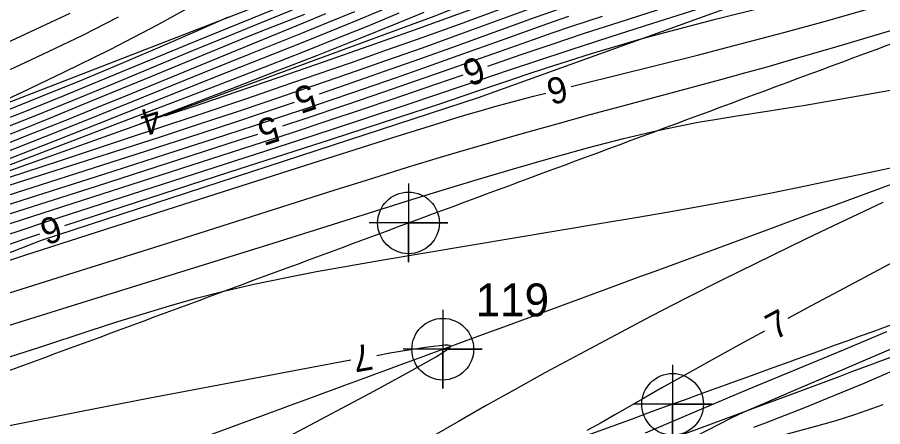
# Model space of a CAD drawing. Extents: x 2602990 to 2605851, y 618069 to 619180.
# Drawn here: x 2603621.3 to 2603687.1, y 618530.5 to 618561.6 of the extents above; entities that cross this region are included whole.
import ezdxf

# ---------------------------------------------------------------- set-up
doc = ezdxf.new("R2010")
doc.units = 0
for name, color, linetype in [('DTM Contours Major', 7, 'Continuous'), ('DTM Contours Major Text', 7, 'Continuous'), ('DTM Contours Minor', 7, 'Continuous'), ('DTM Contours Minor Text', 7, 'Continuous'), ('Exist DTM Breakline', 7, 'Continuous'), ('Exist DTM Crownline', 7, 'Continuous'), ('Exist DTM Crownline Cogo Number', 7, 'Continuous'), ('Exist DTM Crownline Cogo Point CELL', 7, 'Continuous'), ('Exist Roads EOP', 7, 'Continuous'), ('Exist Roads EOP Cogo Point CELL', 7, 'Continuous'), ('PH Exist DTM Breakline', 7, 'Continuous')]:
    doc.layers.add(name, color=color, linetype=linetype)

# ---------------------------------------------------------------- blocks, each defined once
blk = doc.blocks.new('EXIST DTM CROWNLINE COGO POINT')
at = {"layer": 'Exist DTM Crownline Cogo Point CELL'}
blk.add_lwpolyline([(0, 0.06), (0, -0.06), (0, 0), (0.06, 0), (-0.06, 0)], dxfattribs=at)
blk.add_circle((0, 0), 0.0469, dxfattribs=at)
blk = doc.blocks.new('EXIST ROADS EOP COGO POINT')
at = {"layer": 'Exist Roads EOP Cogo Point CELL'}
blk.add_lwpolyline([(0, 0.06), (0, -0.06), (0, 0), (0.06, 0), (-0.06, 0)], dxfattribs=at)
blk.add_circle((0, 0), 0.0469, dxfattribs=at)

msp = doc.modelspace()

# ---------------------------------------------------------------- linework, layer by layer
at = {"layer": 'DTM Contours Major'}
for points in [[(2603624.935, 618545.771), (2603626.021, 618546.13), (2603629.438, 618547.248), (2603637.398, 618549.827), (2603645.213, 618552.351), (2603650.317, 618554.009), (2603653.432, 618555.038), (2603656.165, 618555.96), (2603658.61, 618556.791), (2603660.004, 618557.259), (2603661.544, 618557.767), (2603663.202, 618558.301), (2603664.953, 618558.85), (2603666.771, 618559.399), (2603668.628, 618559.937), (2603670.546, 618560.465), (2603672.469, 618560.972), (2603674.386, 618561.462), (2603678.162, 618562.411)], [(2603637.358, 618561.62), (2603635.026, 618560.586), (2603632.324, 618559.413), (2603629.374, 618558.154), (2603626.3, 618556.865), (2603623.222, 618555.601), (2603620.265, 618554.416), (2603619.145, 618553.977), (2603618.05, 618553.555), (2603616.97, 618553.144), (2603615.891, 618552.742), (2603614.802, 618552.343), (2603613.691, 618551.942), (2603610.655, 618550.877), (2603607.494, 618549.799), (2603604.321, 618548.735), (2603598.384, 618546.757), (2603595.845, 618545.899), (2603594.187, 618545.324), (2603592.708, 618544.798), (2603590.596, 618544.03), (2603587.542, 618542.911), (2603586.705, 618542.609), (2603584.916, 618541.972)], [(2603583.669, 618530.573), (2603588.135, 618532.287), (2603590.546, 618533.197), (2603610.988, 618540.791), (2603616.719, 618542.909), (2603618.996, 618543.735), (2603620.082, 618544.121), (2603621.895, 618544.752), (2603623.038, 618545.137)], [(2603689.392, 618535.379), (2603685.655, 618533.76), (2603682.318, 618532.372), (2603681.15, 618531.909), (2603678.149, 618530.747), (2603677.269, 618530.396)]]:
    msp.add_lwpolyline(points, dxfattribs=at)
at = {"layer": 'DTM Contours Minor'}
for points in [[(2603581.739, 618530.696), (2603587.925, 618533.097), (2603589.528, 618533.709), (2603591.102, 618534.299), (2603598.1, 618536.876), (2603610.103, 618541.323), (2603613.987, 618542.753), (2603616.141, 618543.536), (2603618.127, 618544.242), (2603619.098, 618544.58), (2603620.189, 618544.952), (2603621.307, 618545.327), (2603623.708, 618546.117), (2603640.295, 618551.482), (2603643.652, 618552.574), (2603647.662, 618553.888), (2603651.114, 618555.038), (2603655.168, 618556.411), (2603658.818, 618557.651), (2603660.651, 618558.262), (2603663.331, 618559.139), (2603666.368, 618560.121), (2603669.621, 618561.164), (2603676.203, 618563.26)], [(2603635.401, 618562.914), (2603631.959, 618561.017), (2603628.344, 618559.146), (2603624.834, 618557.41), (2603621.71, 618555.918), (2603618.941, 618554.634), (2603617.838, 618554.139), (2603617.273, 618553.897), (2603616.758, 618553.691), (2603616.187, 618553.479), (2603615.47, 618553.226), (2603613.165, 618552.439), (2603610.041, 618551.39), (2603607.893, 618550.673)], [(2603659.771, 618562.855), (2603654.897, 618561.075), (2603651.719, 618559.932), (2603649.237, 618559.052), (2603646.686, 618558.157), (2603644.077, 618557.251), (2603641.422, 618556.338), (2603638.735, 618555.422), (2603634.816, 618554.1), (2603629.666, 618552.383), (2603624.505, 618550.677), (2603620.636, 618549.409), (2603618.129, 618548.599)], [(2603657.242, 618562.722), (2603653.242, 618561.274), (2603651.486, 618560.646), (2603648.038, 618559.425), (2603644.562, 618558.206), (2603641.196, 618557.038), (2603638.077, 618555.963), (2603635.342, 618555.03), (2603632.52, 618554.08)], [(2603640.896, 618562.233), (2603638.198, 618561.139), (2603635.096, 618559.864), (2603628.275, 618557.046), (2603624.851, 618555.641), (2603621.616, 618554.331), (2603620.027, 618553.699), (2603618.506, 618553.103), (2603617.028, 618552.534), (2603615.568, 618551.984), (2603614.101, 618551.444), (2603612.601, 618550.903), (2603609.985, 618549.986), (2603607.282, 618549.061), (2603599.402, 618546.404), (2603597.102, 618545.614), (2603596.063, 618545.249), (2603594.155, 618544.562), (2603592.403, 618543.915), (2603587.795, 618542.179), (2603585.767, 618541.429)], [(2603586.029, 618540.695), (2603588.38, 618541.586), (2603592.827, 618543.293), (2603594.926, 618544.083), (2603596.02, 618544.487), (2603597.158, 618544.9), (2603598.349, 618545.324), (2603600.382, 618546.032), (2603604.788, 618547.535), (2603607.085, 618548.317), (2603609.393, 618549.113), (2603611.674, 618549.916), (2603613.486, 618550.571), (2603615.277, 618551.234), (2603617.068, 618551.913), (2603618.879, 618552.615), (2603620.733, 618553.347), (2603622.649, 618554.116), (2603625.511, 618555.284), (2603628.473, 618556.507), (2603634.42, 618558.978), (2603637.262, 618560.155), (2603639.924, 618561.245), (2603643.363, 618562.631)], [(2603605.388, 618545.666), (2603607.602, 618546.474), (2603608.879, 618546.945), (2603611.531, 618547.937), (2603614.395, 618549.025), (2603617.386, 618550.176), (2603620.424, 618551.358), (2603623.426, 618552.538), (2603626.308, 618553.685), (2603630.123, 618555.223), (2603635.421, 618557.377), (2603639.082, 618558.852), (2603642.992, 618560.424), (2603644.97, 618561.23), (2603646.962, 618562.057)], [(2603609.83, 618546.66), (2603610.872, 618547.058), (2603614.146, 618548.318), (2603617.581, 618549.647), (2603621.049, 618550.996), (2603624.421, 618552.317), (2603627.569, 618553.56), (2603632.087, 618555.364), (2603636.31, 618557.053), (2603642.915, 618559.672), (2603645.164, 618560.577), (2603647.394, 618561.489), (2603649.577, 618562.405)], [(2603661.273, 618562.606), (2603655.137, 618560.371), (2603652.083, 618559.275), (2603649.309, 618558.295), (2603647.077, 618557.514), (2603644.797, 618556.725), (2603642.5, 618555.937), (2603640.213, 618555.16), (2603637.966, 618554.406), (2603635.066, 618553.446), (2603632.094, 618552.478), (2603628.862, 618551.437), (2603614.842, 618546.96)], [(2603662.58, 618562.269), (2603660.69, 618561.591), (2603654.682, 618559.416), (2603651.456, 618558.269), (2603649.645, 618557.633), (2603647.753, 618556.975), (2603645.797, 618556.299), (2603644.256, 618555.772)], [(2603669.949, 618562.165), (2603667.103, 618561.249), (2603664.407, 618560.369), (2603661.945, 618559.553), (2603659.584, 618558.75), (2603657.068, 618557.874)], [(2603663.422, 618556.339), (2603664.114, 618556.514), (2603669.859, 618557.947), (2603673.016, 618558.744), (2603676.28, 618559.585), (2603679.587, 618560.464), (2603682.739, 618561.33), (2603685.827, 618562.203)], [(2603628.985, 618561.613), (2603626.263, 618560.23), (2603623.706, 618558.999), (2603621.457, 618557.952), (2603618.881, 618556.776), (2603616.887, 618555.881), (2603615.955, 618555.475), (2603614.95, 618555.053), (2603613.463, 618554.456), (2603611.651, 618553.739), (2603609.082, 618552.713), (2603603.078, 618550.297), (2603600.053, 618549.085), (2603597.285, 618547.988), (2603594.979, 618547.095), (2603594.15, 618546.784), (2603593.426, 618546.52), (2603592.782, 618546.291), (2603591.63, 618545.897), (2603589.076, 618545.036), (2603583.905, 618543.258)], [(2603625.312, 618561.902), (2603623.474, 618561.034), (2603618.929, 618558.932), (2603617.454, 618558.236), (2603616.099, 618557.594), (2603615.418, 618557.283), (2603614.722, 618556.978), (2603613.999, 618556.678), (2603613.358, 618556.426), (2603612.684, 618556.173), (2603609.551, 618555.034), (2603607.193, 618554.146), (2603604.587, 618553.14), (2603599.126, 618551.013), (2603596.515, 618550.01), (2603594.148, 618549.126), (2603592.89, 618548.674), (2603591.731, 618548.272), (2603590.639, 618547.905), (2603589.216, 618547.443), (2603587.787, 618546.997), (2603586.28, 618546.542), (2603584.611, 618546.053)], [(2603616.224, 618547.989), (2603613.914, 618547.261), (2603611.786, 618546.629), (2603610.963, 618546.461), (2603611.676, 618546.832), (2603613.678, 618547.657), (2603616.617, 618548.81), (2603620.139, 618550.165), (2603628.935, 618553.523), (2603635.234, 618555.947), (2603640.537, 618558.003), (2603643.128, 618559.02), (2603645.644, 618560.021), (2603648.059, 618561), (2603650.348, 618561.952)], [(2603663.215, 618561.67), (2603661.54, 618561.082), (2603658.38, 618559.953), (2603654.812, 618558.671), (2603652.195, 618557.745), (2603650.028, 618556.988), (2603646.805, 618555.876), (2603645.084, 618555.29), (2603643.296, 618554.686), (2603641.443, 618554.066), (2603639.324, 618553.364), (2603637.138, 618552.647), (2603632.596, 618551.174), (2603627.878, 618549.662), (2603619.976, 618547.14), (2603617.475, 618546.334), (2603615.575, 618545.714)], [(2603618.032, 618539.801), (2603624.346, 618541.803), (2603633.469, 618544.662), (2603638.005, 618546.099), (2603645.469, 618548.48), (2603647.849, 618549.234), (2603650.975, 618550.21), (2603653.496, 618550.979), (2603655.198, 618551.486), (2603657.482, 618552.149), (2603659.877, 618552.83), (2603662.345, 618553.519), (2603664.848, 618554.207), (2603667.35, 618554.887), (2603674.797, 618556.886), (2603676.513, 618557.356), (2603678.304, 618557.855), (2603680.196, 618558.394), (2603683.525, 618559.369), (2603690.594, 618561.476)], [(2603618.184, 618551.097), (2603619.877, 618551.755), (2603622.493, 618552.786), (2603625.077, 618553.818), (2603627.354, 618554.739), (2603629.58, 618555.647), (2603637.996, 618559.107), (2603643.075, 618561.184), (2603644.777, 618561.891)], [(2603619.36, 618552.179), (2603621.585, 618553.061), (2603623.839, 618553.968), (2603626.407, 618555.017), (2603631.544, 618557.142), (2603634.059, 618558.185), (2603636.501, 618559.19), (2603638.842, 618560.142), (2603640.311, 618560.73), (2603643.174, 618561.861)], [(2603630.632, 618553.488), (2603630.663, 618553.506), (2603630.96, 618553.632), (2603632.268, 618554.143), (2603637.944, 618556.323), (2603640.926, 618557.477), (2603644.078, 618558.708), (2603647.243, 618559.963), (2603650.266, 618561.186), (2603652.247, 618562.006)], [(2603665.764, 618561.685), (2603663.454, 618560.912), (2603661.955, 618560.399), (2603660.54, 618559.909), (2603657.938, 618558.99), (2603654.271, 618557.688), (2603651.637, 618556.767), (2603649.142, 618555.907), (2603646.342, 618554.954), (2603643.184, 618553.897), (2603641.465, 618553.329)], [(2603726.536, 618561.87), (2603722.845, 618560.091), (2603718.905, 618558.248), (2603715.103, 618556.486), (2603712.943, 618555.478), (2603710.954, 618554.542), (2603709.102, 618553.662), (2603707.352, 618552.822), (2603705.67, 618552.007), (2603704.021, 618551.201), (2603701.846, 618550.128), (2603699.653, 618549.035), (2603697.428, 618547.914), (2603695.157, 618546.757), (2603692.824, 618545.556), (2603690.416, 618544.303), (2603687.512, 618542.775), (2603684.563, 618541.209), (2603681.649, 618539.649), (2603679.877, 618538.692)], [(2603655.179, 618557.216), (2603653.096, 618556.49), (2603649.793, 618555.359), (2603647.539, 618554.598), (2603644.914, 618553.724), (2603642.205, 618552.833), (2603639.234, 618551.864), (2603632.942, 618549.827), (2603623.267, 618546.717), (2603621.61, 618546.181), (2603620.037, 618545.668), (2603618.533, 618545.169), (2603617.083, 618544.679), (2603615.25, 618544.043), (2603613.386, 618543.378), (2603611.396, 618542.657), (2603606.713, 618540.935), (2603599.282, 618538.191), (2603595.857, 618536.938), (2603592.725, 618535.8), (2603590.819, 618535.096), (2603589.775, 618534.702), (2603587.722, 618533.913), (2603580.003, 618530.886)], [(2603618.259, 618537.431), (2603625.517, 618539.695), (2603640.777, 618544.429), (2603644.88, 618545.715), (2603651.375, 618547.767), (2603653.933, 618548.56), (2603656.376, 618549.303), (2603659.044, 618550.095), (2603661.837, 618550.898), (2603664.656, 618551.674), (2603667.4, 618552.386), (2603669.969, 618552.996), (2603671.578, 618553.337), (2603673.081, 618553.626), (2603674.5, 618553.873), (2603675.857, 618554.093), (2603678.472, 618554.495), (2603679.744, 618554.697), (2603681.037, 618554.908), (2603682.373, 618555.133), (2603685.247, 618555.633), (2603686.823, 618555.913), (2603689.501, 618556.398)], [(2603616.885, 618541.88), (2603621.896, 618543.511), (2603630.809, 618546.373), (2603642.606, 618550.154), (2603649.778, 618552.439), (2603653.043, 618553.466), (2603654.894, 618554.032), (2603655.768, 618554.292), (2603656.686, 618554.558), (2603657.606, 618554.818), (2603658.546, 618555.077), (2603659.521, 618555.339), (2603660.55, 618555.609), (2603661.483, 618555.849)], [(2603642.362, 618555.129), (2603641.754, 618554.923), (2603639.701, 618554.235), (2603637.908, 618553.64), (2603634.257, 618552.445), (2603630.409, 618551.203), (2603619.156, 618547.611), (2603616.152, 618546.647), (2603613.344, 618545.738), (2603610.218, 618544.707), (2603608.516, 618544.131), (2603606.42, 618543.405), (2603601.317, 618541.6), (2603597.096, 618540.122), (2603595.595, 618539.59), (2603594.06, 618539.036), (2603592.499, 618538.461), (2603590.71, 618537.784), (2603588.908, 618537.087), (2603587.108, 618536.376), (2603585.321, 618535.661)], [(2603639.565, 618552.705), (2603638.183, 618552.253), (2603632.783, 618550.504), (2603627.38, 618548.77), (2603620.787, 618546.66), (2603618.767, 618546.006), (2603616.846, 618545.375), (2603615.029, 618544.766), (2603613.338, 618544.185), (2603611.685, 618543.603), (2603609.999, 618542.998), (2603606.257, 618541.633), (2603600.405, 618539.485), (2603597.253, 618538.342), (2603593.646, 618537.044), (2603592.489, 618536.622), (2603591.344, 618536.199), (2603590.059, 618535.714), (2603588.782, 618535.223), (2603586.253, 618534.234), (2603578.503, 618531.159)], [(2603619.031, 618535.237), (2603623.024, 618536.519), (2603626.869, 618537.777), (2603628.891, 618538.433), (2603630.889, 618539.064), (2603632.891, 618539.667), (2603634.923, 618540.239), (2603637.012, 618540.776), (2603639.296, 618541.305), (2603641.654, 618541.798), (2603644.067, 618542.262), (2603646.515, 618542.704), (2603648.981, 618543.13), (2603665.878, 618545.97), (2603668.33, 618546.386), (2603670.828, 618546.818), (2603673.374, 618547.27), (2603675.974, 618547.748), (2603678.633, 618548.26), (2603681.354, 618548.811), (2603684.102, 618549.394), (2603686.753, 618549.962), (2603689.14, 618550.455)], [(2603687.101, 618547.534), (2603683.832, 618545.986), (2603681.29, 618544.767), (2603678.745, 618543.527), (2603677.445, 618542.886), (2603674.873, 618541.603), (2603672.216, 618540.257), (2603669.508, 618538.863), (2603666.782, 618537.438), (2603664.073, 618535.996), (2603661.414, 618534.554), (2603659.152, 618533.303), (2603656.962, 618532.072), (2603654.853, 618530.869), (2603652.831, 618529.704), (2603650.906, 618528.585), (2603646.722, 618526.134), (2603644.485, 618524.807), (2603643.386, 618524.146), (2603642.793, 618523.785)], [(2603678.119, 618537.739), (2603676.239, 618536.716), (2603673.901, 618535.431), (2603671.996, 618534.372), (2603670.308, 618533.42), (2603668.743, 618532.521), (2603666.746, 618531.363), (2603665.708, 618530.771), (2603664.609, 618530.164)], [(2603687.378, 618537.684), (2603684.081, 618536.295), (2603676.801, 618533.262), (2603672.967, 618531.652), (2603669.042, 618529.979)], [(2603648.638, 618535.893), (2603649.646, 618536.073), (2603652.348, 618536.513), (2603652.933, 618536.595), (2603653.412, 618536.653), (2603653.611, 618536.671), (2603653.783, 618536.683), (2603653.929, 618536.687), (2603654.047, 618536.682), (2603654.137, 618536.67), (2603654.199, 618536.648), (2603654.233, 618536.617), (2603654.238, 618536.576), (2603654.218, 618536.528), (2603654.173, 618536.472), (2603654.105, 618536.407), (2603654.013, 618536.332), (2603653.897, 618536.248), (2603653.659, 618536.088), (2603653.169, 618535.786), (2603653.024, 618535.701), (2603651.079, 618534.604), (2603648.436, 618533.174), (2603641.905, 618529.698)], [(2603687.717, 618536.365), (2603683.637, 618534.62), (2603680.304, 618533.186), (2603677.911, 618532.151), (2603676.729, 618531.637), (2603676.169, 618531.386), (2603675.521, 618531.078), (2603674.651, 618530.638), (2603672.877, 618529.721)], [(2603584.153, 618521.774), (2603588.217, 618523.102), (2603591.807, 618524.25), (2603594.672, 618525.128), (2603595.429, 618525.349), (2603596.097, 618525.536), (2603596.699, 618525.696), (2603597.255, 618525.835), (2603597.788, 618525.96), (2603598.76, 618526.172), (2603600.24, 618526.47), (2603604.192, 618527.254), (2603616.144, 618529.642), (2603620.986, 618530.605), (2603626.076, 618531.61), (2603631.391, 618532.65), (2603636.627, 618533.662), (2603641.563, 618534.601), (2603645.977, 618535.42), (2603646.668, 618535.543)], [(2603687.103, 618532.134), (2603684.953, 618531.371), (2603683.524, 618530.921), (2603682.154, 618530.524), (2603679.564, 618529.813)]]:
    msp.add_lwpolyline(points, dxfattribs=at)
at = {"layer": 'Exist DTM Breakline'}
msp.add_spline([(2603647.352, 618520.802), (2603704.337, 618541.966), (2603758.983, 618562.663), (2603811.118, 618582.434), (2603865.604, 618602.567), (2603913.966, 618621.231), (2603963.574, 618640.143), (2603974.725, 618636.355), (2603978.77, 618630.138), (2603971.844, 618627.992), (2603956.88, 618621.982), (2603923.969, 618609.772), (2603877.426, 618591.796), (2603827.273, 618571.857), (2603776.875, 618552.809), (2603720.479, 618530.104), (2603675.109, 618514.176), (2603657.355, 618505.354), (2603640.368, 618498.804), (2603619.191, 618491.366), (2603591.676, 618480.386)], degree=3, dxfattribs=at)
at = {"layer": 'Exist DTM Crownline'}
msp.add_spline([(2603233.488, 618380.754), (2603285.185, 618400.095), (2603335.457, 618418.629), (2603390.812, 618439.069), (2603440.087, 618457.325), (2603493.996, 618477.231), (2603542.655, 618495.301), (2603600.808, 618516.867), (2603653.659, 618536.362), (2603706.222, 618555.742), (2603764.811, 618577.593), (2603823.52, 618599.847), (2603878.564, 618620.56), (2603937.951, 618643.078), (2603997.369, 618665.789), (2604036.209, 618680.665), (2604055.311, 618688.017)], degree=3, dxfattribs=at)
at = {"layer": 'Exist Roads EOP'}
for points in [[(2603230.17, 618389.98), (2603282.929, 618409.597), (2603332.773, 618427.868), (2603388.167, 618448.413), (2603437.203, 618466.721), (2603490.778, 618486.527), (2603539.039, 618504.558), (2603597.451, 618526.156), (2603651.053, 618545.972), (2603705.208, 618566.084), (2603762.02, 618587.183), (2603820.334, 618609.162), (2603876.341, 618629.99), (2603934.909, 618652.28), (2603996.409, 618675.568), (2604033.216, 618689.957), (2604052.01, 618697.199)], [(2604034.633, 618668.486), (2603984.89, 618650.123), (2603936.767, 618631.654), (2603888.195, 618613.335), (2603837.766, 618594.258), (2603782.918, 618573.705), (2603731.939, 618554.39), (2603671.126, 618532.171), (2603621.822, 618514.106), (2603561.545, 618491.877), (2603506.421, 618471.293), (2603452.163, 618451.33), (2603398.364, 618431.316), (2603341.431, 618410.355), (2603281.65, 618388.199), (2603223.033, 618366.475), (2603185.717, 618352.612)]]:
    msp.add_spline(points, degree=3, dxfattribs=at)
at = {"layer": 'PH Exist DTM Breakline'}
for points in [[(2603705.164, 618577.697), (2603705.091, 618579.589), (2603704.663, 618581.271), (2603703.724, 618582.897), (2603701.827, 618583.336), (2603697.541, 618582.418), (2603687.253, 618578.721), (2603678.174, 618576.623), (2603666.102, 618572.394), (2603643.492, 618564.006), (2603616.812, 618553.628), (2603590.871, 618545.866), (2603571.822, 618539.052), (2603544.534, 618528.258), (2603518.966, 618519.12), (2603485.62, 618505.853), (2603447.747, 618490.489), (2603438.798, 618485.938), (2603436.118, 618483.299), (2603434.252, 618481.3)], [(2603435.879, 618478.915), (2603449.565, 618484.741), (2603462.026, 618490.881), (2603491.087, 618501.598), (2603513.203, 618510.293), (2603534.552, 618518.577), (2603557.552, 618526.043), (2603578.968, 618534.328), (2603593.177, 618540.018), (2603605.222, 618544.41), (2603632.452, 618554.135), (2603653.005, 618561.707), (2603674.385, 618570.193), (2603686.907, 618573.987), (2603694.343, 618577.121), (2603698.717, 618578.477), (2603701.98, 618580.257)], [(2603433.996, 618481.025), (2603435.039, 618479.196), (2603436.539, 618477.73), (2603439.924, 618476.848), (2603445.649, 618477.117), (2603451.918, 618478.979), (2603471.67, 618486.926), (2603497.083, 618496.164), (2603518.517, 618504.591), (2603548.361, 618515.465), (2603589.296, 618531.427), (2603623.154, 618544.648), (2603656.373, 618555.51), (2603681.075, 618564.434), (2603699.669, 618570.731)]]:
    msp.add_lwpolyline(points, dxfattribs=at)

# ---------------------------------------------------------------- block references
at = {"layer": 'Exist DTM Crownline Cogo Point CELL', "xscale": 50, "yscale": 50}
msp.add_blockref('EXIST DTM CROWNLINE COGO POINT', (2603653.659, 618536.362), dxfattribs=at)
at = {"layer": 'Exist Roads EOP Cogo Point CELL', "xscale": 50, "yscale": 50}
for p in [(2603651.053, 618545.972), (2603671.126, 618532.171)]:
    msp.add_blockref('EXIST ROADS EOP COGO POINT', p, dxfattribs=at)

# ---------------------------------------------------------------- texts
at = {"layer": 'DTM Contours Major Text'}
msp.add_text('6', height=2, rotation=198.50312, dxfattribs=at).set_placement((2603624.288, 618546.612))
at = {"layer": 'DTM Contours Minor Text'}
for s, rotation, p in [('6', 199.20556, (2603656.412, 618558.704)), ('6', 194.18743, (2603662.841, 618557.224)), ('5', 198.75719, (2603643.607, 618556.607)), ('4', 197.42193, (2603631.894, 618554.917)), ('5', 198.17728, (2603640.824, 618554.17)), ('7', 28.44904, (2603678.899, 618537.026)), ('7', 190.08474, (2603648.121, 618536.817))]:
    msp.add_text(s, height=2, rotation=rotation, dxfattribs=at).set_placement(p)
at = {"layer": 'Exist DTM Crownline Cogo Number'}
msp.add_text('119', height=2.5, dxfattribs=at).set_placement((2603656.159, 618538.862))

doc.saveas('drawing.dxf')
